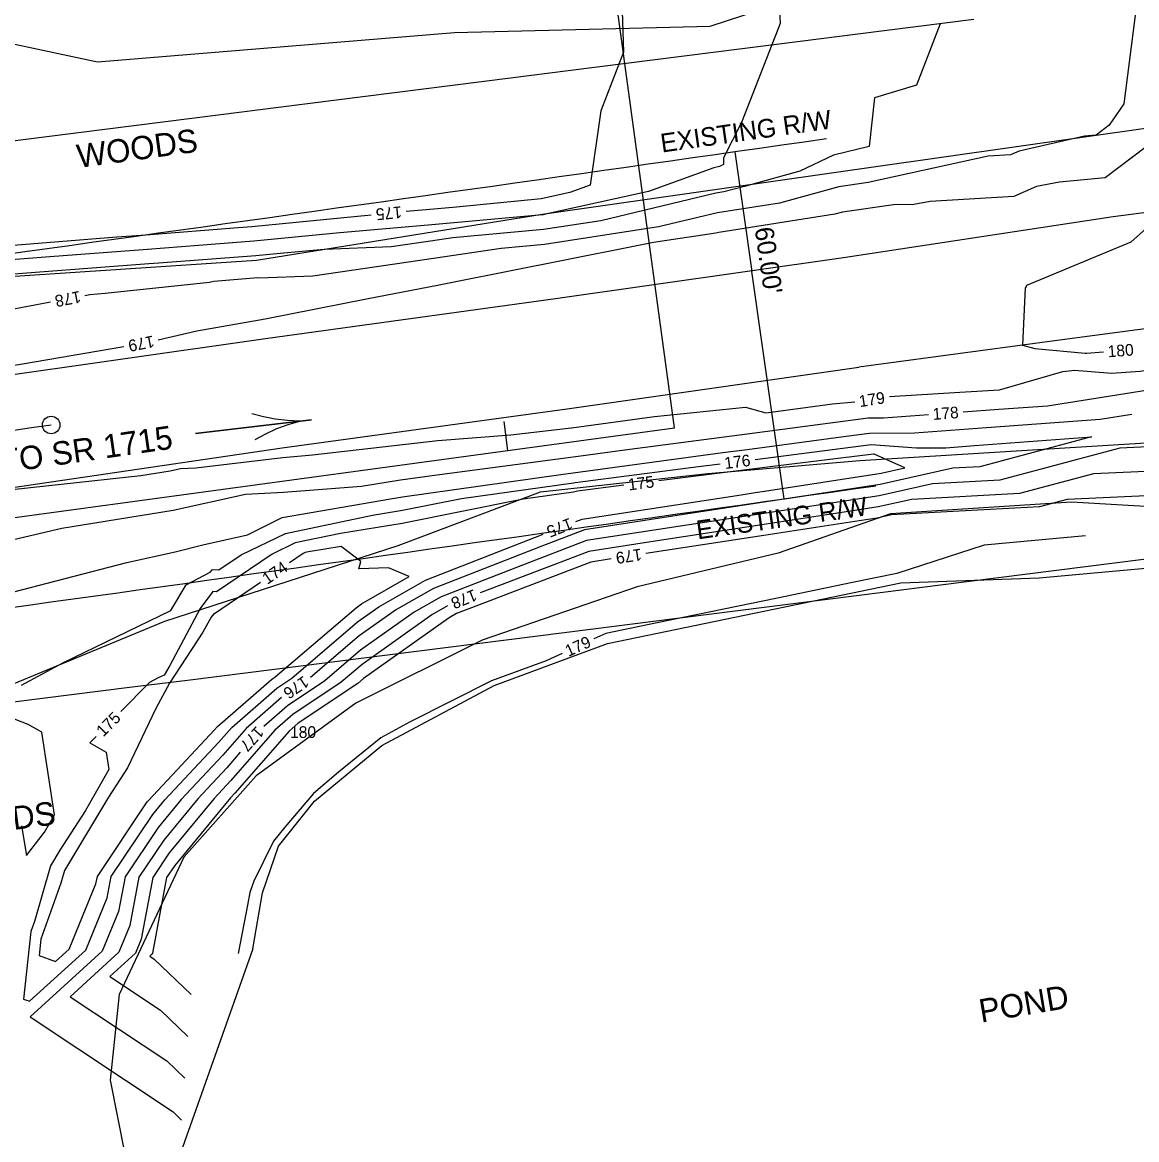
# Model space of a CAD drawing. Extents: x 2086416 to 2115205, y 575507 to 632762.
# Drawn here: x 2112506.7 to 2112697.5, y 581663.7 to 581854.9 of the extents above; entities that cross this region are included whole.
import ezdxf

# ---------------------------------------------------------------- set-up
doc = ezdxf.new("R2010")
doc.units = 0
for name, color, linetype in [('Default', 7, 'Continuous'), ('DTM Contours Major', 7, 'Continuous'), ('DTM Contours Major Text', 7, 'Continuous'), ('DTM Contours Minor', 7, 'Continuous'), ('DTM Contours Minor Text', 7, 'Continuous'), ('Exist Hydro Stream or Body of Water', 7, 'Continuous'), ('Exist Hydro Stream or Body of Water Text', 7, 'Continuous'), ('Exist Hydrographic FEMA Cross Section', 7, 'Continuous'), ('Exist Right of Way Line', 7, 'Continuous'), ('Exist Right of Way Line Text', 7, 'Continuous'), ('Exist Right of Way Width CELL', 7, 'Continuous'), ('Exist Roads EOP', 7, 'Continuous'), ('Exist Roads EOP Text', 7, 'Continuous'), ('Exist Vegetation Woods Line', 7, 'Continuous'), ('Exist Vegetation Woods Line Text', 7, 'Continuous'), ('Prop Horizontal Alignment', 7, 'Continuous'), ('Prop Horizontal Alignment Station Label', 7, 'Continuous')]:
    doc.layers.add(name, color=color, linetype=linetype)

msp = doc.modelspace()

# ---------------------------------------------------------------- linework, layer by layer
at = {"layer": 'Default'}
for p, q in [((2112618.34, 581785.48), (2112603.31, 581895.93)), ((2112048.04, 581707.89), (2112618.34, 581785.48)), ((2112589.85, 581781.61), (2112589.18, 581786.56))]:
    msp.add_line(p, q, dxfattribs=at)
at = {"layer": 'DTM Contours Major'}
for points in [[(2112636.91, 581872.16), (2112609.11, 581865.6), (2112609.65, 581849.73), (2112605.74, 581839.73), (2112603.91, 581826.98), (2112600.43, 581825.74), (2112595.52, 581824.65), (2112581.05, 581823.24), (2112575.88, 581822.78), (2112572.42, 581822.47)], [(2112748.09, 581837.55), (2112741.55, 581835.69), (2112736.14, 581832.79), (2112725.63, 581829.67), (2112721.96, 581827.49), (2112720.23, 581827.33), (2112702.76, 581822.86), (2112696.49, 581817.23), (2112678.63, 581809.81), (2112678.51, 581809.48), (2112678.39, 581809.46), (2112677.94, 581799.62), (2112680.05, 581799.06), (2112688.65, 581798.24), (2112688.86, 581798.27), (2112688.88, 581798.27), (2112691.79, 581798.49)], [(2112566.44, 581821.89), (2112546.02, 581819.89), (2112543.66, 581819.72), (2112527.89, 581818.46), (2112522.91, 581818.08), (2112498, 581816.1), (2112494.05, 581815.66), (2112475.27, 581812.96), (2112469.71, 581812.32), (2112466.97, 581811.93)], [(2112601.47, 581769.44), (2112602.57, 581769.86), (2112629.75, 581774.03), (2112632.19, 581774.4), (2112633.74, 581774.64), (2112653.74, 581777.71), (2112657.78, 581778.62), (2112652.55, 581780.98), (2112652.4, 581780.99), (2112635.17, 581778.85), (2112631.57, 581778.39), (2112615.66, 581776.4)], [(2112609.7, 581775.65), (2112601.75, 581774.62), (2112601.09, 581774.49), (2112592.48, 581773.28), (2112571.76, 581769.13), (2112561.18, 581767.4), (2112553.45, 581765.78), (2112549.49, 581763.87), (2112539.99, 581757.41), (2112539.36, 581757.46), (2112537.18, 581754.54), (2112531.99, 581744.84), (2112530.98, 581743.17), (2112529.99, 581742.69), (2112528.52, 581741.89), (2112523.6, 581736.94)], [(2112521.27, 581705.07), (2112521.94, 581708.68), (2112529.05, 581719.29), (2112531.14, 581721.83), (2112540.33, 581731.64), (2112542.58, 581734.21), (2112550.28, 581740.92), (2112552.84, 581742.63), (2112564.12, 581752.28), (2112567.77, 581754.87), (2112575.75, 581759.43), (2112595.88, 581767.27)], [(2112519.37, 581732.69), (2112518.28, 581731.59), (2112521.06, 581729.99), (2112521.52, 581727), (2112517.52, 581720.02), (2112513.17, 581713.23), (2112511.55, 581710.54), (2112508.79, 581701), (2112508.19, 581699.3), (2112506.93, 581687.74), (2112507.98, 581687.37), (2112517.58, 581696.12), (2112521.27, 581705.07)], [(2112554.83, 581733.42), (2112554.9, 581733.47), (2112555, 581733.49), (2112554.91, 581733.42), (2112554.84, 581733.36), (2112554.76, 581733.35), (2112554.82, 581733.42), (2112554.83, 581733.42)]]:
    msp.add_lwpolyline(points, dxfattribs=at)
at = {"layer": 'DTM Contours Minor'}
for points in [[(2112645.97, 581862.98), (2112640.96, 581858.15), (2112636.36, 581857.07), (2112636.44, 581854.64), (2112629.82, 581837.7), (2112626.77, 581831.69), (2112626.76, 581830.54), (2112626.08, 581830.21), (2112625.08, 581829.94), (2112613.9, 581825.94), (2112596.28, 581822.03), (2112595.89, 581821.94), (2112595.73, 581821.92), (2112595.14, 581821.86), (2112576.22, 581820.18), (2112561.06, 581818.84), (2112546.35, 581817.4), (2112536.87, 581816.69), (2112528.13, 581815.99), (2112511.43, 581814.74), (2112498.22, 581813.69), (2112487.5, 581812.49), (2112476.22, 581810.87), (2112468.78, 581810.01)], [(2112697.42, 581857.86), (2112695.28, 581840.91), (2112692.79, 581837.25), (2112690.56, 581835.55), (2112688.56, 581835.37), (2112677.37, 581832.83), (2112675.87, 581832.17), (2112672.05, 581831.94), (2112651.52, 581827.43), (2112646.49, 581826.71), (2112636.31, 581823.94), (2112625.7, 581822.28), (2112615.6, 581819.85), (2112596.09, 581816.86), (2112588.69, 581816.19), (2112577.09, 581814.47), (2112556.48, 581811.43), (2112547.27, 581811.07), (2112547.04, 581811.16), (2112539.5, 581810.54), (2112538.76, 581810.37), (2112520.89, 581808.45), (2112518.28, 581808.23), (2112517.45, 581808.07)], [(2112663.86, 581854.6), (2112659.78, 581844.09), (2112652.58, 581841.93), (2112651.7, 581833.6), (2112645.57, 581832.16), (2112639.8, 581829.4), (2112630.34, 581826.8), (2112626.8, 581825.84), (2112625.46, 581825.63), (2112605.75, 581820.9), (2112595.91, 581819.39), (2112580.44, 581817.98), (2112576.62, 581817.42), (2112569.85, 581816.42), (2112558.4, 581815.98), (2112550.21, 581815.25), (2112546.68, 581814.9), (2112530.08, 581813.66), (2112528.36, 581813.52), (2112499.94, 581811.39), (2112498.45, 581811.27), (2112481.31, 581809.36)], [(2112723.83, 581841.15), (2112721.75, 581839.66), (2112716.25, 581836.4), (2112706.66, 581835.52), (2112699.07, 581833.57), (2112692.09, 581828.23), (2112684.27, 581827.52), (2112680.34, 581826.8), (2112676.46, 581825.08), (2112662.13, 581824.22), (2112659.35, 581823.7), (2112655.86, 581823.66), (2112647.11, 581822.39), (2112645.82, 581822.04), (2112625.94, 581818.92), (2112625.46, 581818.8), (2112614.79, 581817.17), (2112596.44, 581813.54), (2112593.26, 581812.92), (2112577.77, 581809.86), (2112565.9, 581807.54), (2112548.29, 581804.06), (2112536.57, 581801.99), (2112529.98, 581800.49)], [(2112655.14, 581790.83), (2112667.2, 581791.57), (2112673.99, 581791.98), (2112684.85, 581795.09), (2112686.89, 581795.36), (2112693.19, 581794.82), (2112698.08, 581795.19), (2112702.91, 581795.99), (2112712.23, 581796.14), (2112723.39, 581797.05), (2112725.62, 581797.41), (2112728.99, 581797.73), (2112736.91, 581800.53), (2112752.16, 581802.53), (2112759.21, 581803.44), (2112763.22, 581804.33), (2112778.23, 581805.29), (2112781.99, 581805.05), (2112789.46, 581805.39), (2112801.81, 581805.92), (2112815.69, 581809.49)], [(2112667.8, 581788.21), (2112673.85, 581788.66), (2112682.18, 581789.27), (2112695.53, 581791.34), (2112699.44, 581791.98), (2112719.29, 581793.6), (2112731.39, 581795.57), (2112733.56, 581795.77), (2112738.64, 581797.56), (2112748.41, 581798.85), (2112759.68, 581800.3), (2112766.1, 581801.73), (2112775.78, 581802.35), (2112778.21, 581802.19), (2112791.8, 581802.81), (2112798.09, 581803.08), (2112817.03, 581807.95), (2112822.07, 581808.79), (2112824, 581804.29), (2112824.19, 581803.96), (2112823.92, 581803.92), (2112804.98, 581797.38), (2112794.7, 581795.17), (2112787.25, 581792.92)], [(2112511.55, 581806.96), (2112499.21, 581804.64), (2112498.43, 581804.49), (2112498.38, 581804.49), (2112478.3, 581802.96), (2112465.71, 581802.63), (2112450.27, 581803.47), (2112448.3, 581803.24), (2112447.97, 581803.2), (2112430.58, 581800.2), (2112430.09, 581800.11), (2112429.15, 581799.94), (2112400.54, 581795), (2112384.3, 581793.55), (2112381.64, 581793.07), (2112380.26, 581792.73), (2112378.47, 581792.78), (2112350.55, 581789.12), (2112334.02, 581788.71), (2112330.91, 581788.37), (2112330.11, 581788.28), (2112313.11, 581786.4)], [(2112524.1, 581799.36), (2112502.35, 581795.63), (2112499.7, 581795.1), (2112483.45, 581793.64), (2112479.62, 581793.35), (2112466.07, 581793), (2112449.37, 581791.76), (2112442.17, 581791.19), (2112430.97, 581789.85), (2112407.55, 581788.67), (2112401.02, 581788.16), (2112397.78, 581787.9), (2112381.2, 581783.86), (2112351.94, 581784.74), (2112351.1, 581784.63), (2112350.45, 581784.61), (2112331.72, 581780.19), (2112325.81, 581780.89)], [(2112810.84, 581793.78), (2112795.16, 581790.41), (2112790.93, 581789.14), (2112766.89, 581784.01), (2112762.05, 581783.26), (2112739.47, 581779.47), (2112734.79, 581778.75), (2112709.85, 581774.56), (2112707.71, 581774.23), (2112685.59, 581773.2), (2112680.84, 581771.94), (2112655.49, 581770.57), (2112653.07, 581770.03), (2112649.99, 581769.55), (2112633.68, 581767.05), (2112613.48, 581763.95)], [(2112781.46, 581791.4), (2112768.47, 581788.63), (2112754.75, 581786.49), (2112740.28, 581784.07), (2112726.56, 581781.93), (2112710.66, 581779.27), (2112704.14, 581778.25), (2112690.09, 581777.6), (2112677.44, 581774.23), (2112659, 581773.24), (2112653.24, 581771.95), (2112645.93, 581770.83), (2112633.3, 581768.89), (2112613.57, 581765.86), (2112603.67, 581764.34), (2112588.42, 581758.52), (2112585.1, 581757.23)], [(2112450.98, 581766.25), (2112453.18, 581766.72), (2112478.09, 581770.73), (2112482.75, 581771.51), (2112484.71, 581771.84), (2112502.32, 581774.65), (2112526.99, 581777.32), (2112532.05, 581778.14), (2112533.78, 581778.52), (2112536.45, 581778.65), (2112551.34, 581780.38), (2112556.38, 581780.85), (2112577.86, 581783.31), (2112590.33, 581784.3), (2112600.7, 581785.45), (2112600.71, 581785.45), (2112614.91, 581787.44), (2112630.49, 581789), (2112634.01, 581788.06), (2112645.38, 581789.57), (2112649.23, 581789.91)], [(2112463.95, 581760.01), (2112475.03, 581761.46), (2112482.99, 581762.8), (2112492.81, 581764.45), (2112503.29, 581765.89), (2112513.46, 581768.32), (2112532.52, 581771.41), (2112544.95, 581774.12), (2112551.45, 581774.45), (2112564.8, 581775.49), (2112571.48, 581776.56), (2112577.3, 581777.39), (2112600.99, 581780.53), (2112601.01, 581780.53), (2112610.73, 581781.85), (2112630.78, 581784.45), (2112636.85, 581785.27), (2112651.51, 581787.18), (2112654.16, 581787.19), (2112661.82, 581787.76)], [(2112499.81, 581756.6), (2112503.48, 581756.96), (2112524.64, 581762.43), (2112532.86, 581764.26), (2112537.64, 581765.46), (2112545.26, 581767.15), (2112551.19, 581770.14), (2112569.72, 581773.31), (2112571.82, 581773.65), (2112598.89, 581777.49), (2112601, 581777.77), (2112601.01, 581777.77), (2112626.66, 581781.25), (2112630.79, 581781.78), (2112647.74, 581784.07), (2112651.73, 581784.59), (2112659.47, 581784.64), (2112671.79, 581785.55), (2112691.22, 581786.98), (2112696.66, 581787.82)], [(2112736.95, 581788.02), (2112718.32, 581785.12), (2112711.47, 581783.97), (2112700.58, 581782.28), (2112694.59, 581782), (2112674.03, 581776.53), (2112662.5, 581775.91), (2112653.4, 581773.87), (2112641.87, 581772.1), (2112632.93, 581770.73), (2112618.96, 581768.59), (2112603.3, 581766.18), (2112592.03, 581761.88), (2112578.41, 581756.57), (2112573.79, 581753.93), (2112564.62, 581747.43), (2112558.49, 581742.19), (2112552.1, 581737.92), (2112548.06, 581734.4)], [(2112632.14, 581780.07), (2112645.4, 581781.78), (2112652.04, 581782.61), (2112659.81, 581782.05), (2112664.79, 581782.08), (2112669.73, 581782.45), (2112689.72, 581783.91), (2112670.63, 581778.83), (2112666, 581778.58), (2112653.57, 581775.79), (2112637.81, 581773.37), (2112632.56, 581772.57), (2112624.36, 581771.31), (2112602.94, 581768.02), (2112595.65, 581765.24), (2112577.08, 581758), (2112570.78, 581754.4), (2112564.37, 581749.86), (2112556.03, 581742.73)], [(2112506.6, 581741.44), (2112513.78, 581745.34), (2112532.12, 581754.22), (2112534.78, 581758.6), (2112538.87, 581760.76), (2112539.25, 581761.26), (2112540.38, 581761.18), (2112544.16, 581763.75), (2112551.78, 581767.42), (2112566.65, 581770.53), (2112571.8, 581771.37), (2112581.89, 581773.4), (2112601.05, 581776.07), (2112601.36, 581776.13), (2112622.47, 581778.86), (2112626.19, 581779.32)], [(2112688.72, 581766.99), (2112671.38, 581765.38), (2112656.41, 581760.58), (2112648.82, 581759.02), (2112635.97, 581756.36), (2112615.12, 581752.04), (2112606.59, 581750.29), (2112604.58, 581749.37)], [(2112519.33, 581707.43), (2112519.57, 581708.72), (2112528.11, 581721.46), (2112528.34, 581721.74), (2112539.64, 581733.81), (2112540.13, 581734.37), (2112549.38, 581742.42), (2112550.01, 581742.85), (2112563.87, 581754.7), (2112564.77, 581755.34), (2112572.96, 581760.03), (2112569.42, 581761.51), (2112564.35, 581761.37), (2112564.68, 581762.61), (2112561.3, 581765.18), (2112555.72, 581764.27), (2112555.12, 581764.14), (2112554.81, 581763.99), (2112552.46, 581762.39)], [(2112607.54, 581763.04), (2112604.03, 581762.5), (2112584.8, 581755.16), (2112581.07, 581753.71), (2112579.81, 581752.99), (2112565.11, 581742.58), (2112564.14, 581741.75), (2112553.92, 581734.92), (2112552.38, 581733.58), (2112543.09, 581722.95), (2112542.35, 581722.16), (2112532.81, 581710.6), (2112531.41, 581708.51), (2112529.01, 581695.6), (2112528.92, 581695.4), (2112528.55, 581695.06), (2112529.29, 581694.57), (2112535.6, 581688.52)], [(2112547.5, 581759.02), (2112539.6, 581753.65), (2112539.48, 581753.66), (2112539.03, 581753.06), (2112537.65, 581750.49), (2112531.92, 581741.79), (2112529.59, 581737.46), (2112524.74, 581727.31), (2112521.5, 581722.26), (2112513.94, 581709.74), (2112513.3, 581707.55), (2112509.9, 581697.96), (2112509.6, 581695.18), (2112512.42, 581694.18), (2112514.74, 581696.3), (2112519.33, 581707.43)], [(2112579.53, 581755.02), (2112576.8, 581753.46), (2112564.87, 581745.01), (2112561.31, 581741.97), (2112553.01, 581736.42), (2112549.93, 581733.74), (2112542.4, 581725.12), (2112539.55, 581722.08), (2112531.87, 581712.78), (2112529.04, 581708.56), (2112527.07, 581697.97), (2112526.09, 581695.58), (2112521.73, 581691.6), (2112530.37, 581685.86), (2112535.07, 581681.35)], [(2112599.13, 581746.88), (2112596.38, 581745.63), (2112587.02, 581742.21), (2112573.14, 581735.16), (2112568.1, 581732.41), (2112560.83, 581726.54), (2112556.58, 581722.92), (2112551.68, 581717.14), (2112549.73, 581714.74), (2112546.37, 581707.9), (2112545.67, 581705.97), (2112545.29, 581703.81), (2112543.68, 581695.51)], [(2112506.56, 581717.37), (2112507.46, 581712.28), (2112510.53, 581716.3), (2112512.23, 581719.27), (2112510.05, 581733.38), (2112507.75, 581734.7), (2112495.36, 581739.51)], [(2112551.09, 581739.33), (2112545.03, 581734.05), (2112541.02, 581729.47), (2112533.94, 581721.91), (2112529.99, 581717.12), (2112524.31, 581708.64), (2112523.2, 581702.7), (2112520.42, 581695.94), (2112508.07, 581684.68), (2112532.54, 581668.43), (2112534, 581667.03)], [(2112544.04, 581729.96), (2112541.71, 581727.3), (2112536.75, 581722), (2112530.93, 581714.95), (2112526.67, 581708.6), (2112525.14, 581700.33), (2112523.25, 581695.76), (2112514.9, 581688.14), (2112531.46, 581677.14), (2112534.53, 581674.19)]]:
    msp.add_lwpolyline(points, dxfattribs=at)
at = {"layer": 'Exist Hydro Stream or Body of Water'}
for points in [[(2112657.1, 581758.96), (2112680.78, 581759.84), (2112713.46, 581762.75), (2112743.23, 581764.08), (2112763.42, 581766.61), (2112786.45, 581770.23), (2112798.77, 581773.29), (2112810.55, 581775.49), (2112822.44, 581776.45), (2112839.49, 581777.68)], [(2112546.19, 581696.31), (2112547.82, 581705.92), (2112550.58, 581713.92), (2112556.73, 581721.61), (2112568.26, 581731.1), (2112587.48, 581741.37), (2112606.9, 581748.57), (2112657.1, 581758.96)], [(2112546.19, 581696.31), (2112533.52, 581660.58), (2112555.77, 581578.76), (2112572.52, 581530.5)]]:
    msp.add_lwpolyline(points, dxfattribs=at)
at = {"layer": 'Exist Hydrographic FEMA Cross Section'}
for points in [[(2112669.6, 581855.32), (2112659.68, 581854.07), (2112649.77, 581852.81), (2112639.85, 581851.56), (2112629.93, 581850.31), (2112620.02, 581849.06), (2112610.1, 581847.81), (2112600.18, 581846.56), (2112590.27, 581845.3), (2112580.35, 581844.05), (2112570.43, 581842.8), (2112560.52, 581841.54), (2112550.6, 581840.29), (2112540.68, 581839.04), (2112530.77, 581837.79), (2112520.85, 581836.54), (2112510.93, 581835.29), (2112501.02, 581834.04)], [(2112703.58, 581763.55), (2112693.67, 581762.3), (2112683.75, 581761.05), (2112673.83, 581759.8), (2112663.92, 581758.54), (2112654, 581757.29), (2112649.04, 581756.66), (2112644.08, 581756.04), (2112634.16, 581754.79), (2112624.24, 581753.53), (2112614.33, 581752.28), (2112604.41, 581751.03), (2112594.49, 581749.78), (2112584.58, 581748.53), (2112574.66, 581747.28), (2112564.74, 581746.02), (2112554.83, 581744.77), (2112544.91, 581743.52), (2112534.99, 581742.27), (2112525.08, 581741.02), (2112515.16, 581739.77), (2112505.24, 581738.51)]]:
    msp.add_lwpolyline(points, dxfattribs=at)
at = {"layer": 'Exist Right of Way Line'}
for radius in [40760.04, 40820.04]:
    msp.add_arc((2106889.07, 622186.64), radius, 277.771006, 278.117244, dxfattribs=at)
at = {"layer": 'Exist Right of Way Width CELL'}
for p in [(2112628.67, 581832.73), (2112637.12, 581773.33)]:
    msp.add_line(p, (2112631.59, 581812.24), dxfattribs=at)
at = {"layer": 'Exist Roads EOP'}
for points in [[(2112647.29, 581814.65), (2112693.46, 581821.64), (2112739.24, 581827.62), (2112774.48, 581832.8), (2112796.9, 581835.72), (2112819.5, 581838.73)], [(2112824.17, 581819.47), (2112799.03, 581816.06), (2112765.01, 581811.56), (2112717.81, 581804.94), (2112683.85, 581800.4), (2112649.9, 581795.88)], [(2112106.04, 581730.56), (2112104.78, 581739.98), (2112155.28, 581747.16), (2112204.05, 581753.61), (2112253.47, 581760.3), (2112302.94, 581766.96), (2112352.11, 581773.79), (2112401.72, 581780.29), (2112450.22, 581786.9), (2112499.86, 581793.89), (2112548.73, 581800.82), (2112597.59, 581807.57), (2112647.29, 581814.65)], [(2112106.04, 581730.56), (2112107.32, 581720.97), (2112157.7, 581727.7), (2112206.75, 581734.2), (2112256.3, 581741.08), (2112305.32, 581747.93), (2112354.53, 581754.87), (2112403.99, 581761.61), (2112453.01, 581768.18), (2112502.29, 581774.88), (2112551.21, 581782.05), (2112600.41, 581788.81), (2112649.9, 581795.88)]]:
    msp.add_lwpolyline(points, dxfattribs=at)
at = {"layer": 'Exist Roads EOP Text'}
msp.add_line((2112546.28, 581785.68), (2112546.28, 581785.68), dxfattribs=at)
msp.add_lwpolyline([(2112546.01, 581787.95), (2112547.98, 581787.4), (2112550.01, 581787), (2112552.09, 581786.77), (2112554.16, 581786.7), (2112556.21, 581786.87), (2112536.35, 581784.49), (2112556.21, 581786.87), (2112554.18, 581786.56), (2112552.18, 581786), (2112550.22, 581785.29), (2112548.33, 581784.42), (2112546.55, 581783.41)], dxfattribs=at)
at = {"layer": 'Exist Vegetation Woods Line'}
for points in [[(2112455.71, 581861.8), (2112519.59, 581848.11), (2112580.68, 581853.15), (2112624.48, 581854.23), (2112655.73, 581864.5)], [(2112755.55, 581849.31), (2112726.93, 581840.45), (2112699.77, 581836.79), (2112652.45, 581830.08)], [(2112652.45, 581830.08), (2112595.73, 581821.98), (2112546.79, 581814.11), (2112498.48, 581810.93), (2112448.01, 581803.1), (2112400.6, 581794.47), (2112350.25, 581791.56), (2112301.36, 581782.95)], [(2112650.08, 581779.87), (2112704.56, 581783.27), (2112778.59, 581795.96), (2112822.78, 581802.04)], [(2112832.5, 581784.96), (2112792.11, 581781.34), (2112731.05, 581770.16), (2112686.29, 581772.77), (2112655.35, 581770.76)], [(2112531.13, 581752.37), (2112571.08, 581765.34), (2112595.42, 581774.53), (2112624.07, 581777.64), (2112650.08, 581779.87)], [(2112655.35, 581770.76), (2112636.11, 581764.04), (2112611.95, 581758.29), (2112585.45, 581749.12), (2112563.82, 581738.35), (2112546.75, 581725.94), (2112534.35, 581712.03), (2112523.3, 581688.5), (2112521.77, 581673.84), (2112526.84, 581648.27), (2112537.4, 581615.32), (2112544.88, 581590.56), (2112553.28, 581562.85)], [(2112111.96, 581666.92), (2112111.49, 581680.94), (2112152.5, 581684.53), (2112262.63, 581685.59), (2112360.38, 581709.42), (2112461.66, 581723.72), (2112531.13, 581752.37)]]:
    msp.add_lwpolyline(points, dxfattribs=at)
at = {"layer": 'Prop Horizontal Alignment'}
msp.add_arc((2106889.07, 622186.64), 40790.04, 277.771006, 277.923, dxfattribs=at)
at = {"layer": 'Prop Horizontal Alignment Station Label'}
msp.add_circle((2112511.66, 581785.97), 1.5, dxfattribs=at)

# ---------------------------------------------------------------- texts
at = {"layer": 'DTM Contours Major Text'}
for s, rotation, p in [('175', 185.5403, (2112571.6, 581823.4)), ('180', 4.3467, (2112692.58, 581797.54)), ('175', 7.1836, (2112610.55, 581774.75)), ('175', 201.1335, (2112600.43, 581770.12)), ('175', 45.1692, (2112520.59, 581732.5))]:
    msp.add_text(s, height=2, rotation=rotation, dxfattribs=at).set_placement(p)
msp.add_text('180', height=2, dxfattribs=at).set_placement((2112552.55, 581732.42))
at = {"layer": 'DTM Contours Minor Text'}
for s, rotation, p in [('178', 190.6478, (2112516.55, 581808.92)), ('179', 190.8944, (2112529.1, 581801.28)), ('179', 8.8481, (2112650.09, 581789.01)), ('178', 4.2658, (2112662.62, 581786.82)), ('176', 7.1662, (2112627.03, 581778.42)), ('179', 188.7197, (2112612.61, 581764.83)), ('174', 34.2117, (2112548.66, 581758.6)), ('178', 201.6387, (2112584.05, 581757.91)), ('179', 24.5162, (2112600.2, 581746.27)), ('176', 214.4626, (2112554.88, 581743.13)), ('177', 227.8624, (2112546.8, 581734.57))]:
    msp.add_text(s, height=2, rotation=rotation, dxfattribs=at).set_placement(p)
at = {"layer": 'Exist Hydro Stream or Body of Water Text'}
msp.add_text('POND', height=4, rotation=9.6236, dxfattribs=at).set_placement((2112670.86, 581683.68))
at = {"layer": 'Exist Right of Way Line Text'}
for rotation, p in [(8.0999, (2112616.2, 581832.57)), (8.0954, (2112622.33, 581766.38))]:
    msp.add_text('EXISTING R/W', height=3.2, rotation=rotation, dxfattribs=at).set_placement(p)
at = {"layer": 'Exist Right of Way Width CELL'}
msp.add_text("60.00'", height=3.2, rotation=278.095, dxfattribs=at).set_placement((2112632.08, 581819.62))
at = {"layer": 'Exist Roads EOP Text'}
msp.add_text('TO SR 1715', height=4, rotation=8.2185, dxfattribs=at).set_placement((2112503.24, 581777.69))
at = {"layer": 'Exist Vegetation Woods Line Text'}
for p in [(2112516.35, 581829.93), (2112492.01, 581714.85)]:
    msp.add_text('WOODS', height=4, rotation=7.771, dxfattribs=at).set_placement(p)

doc.saveas('drawing.dxf')
